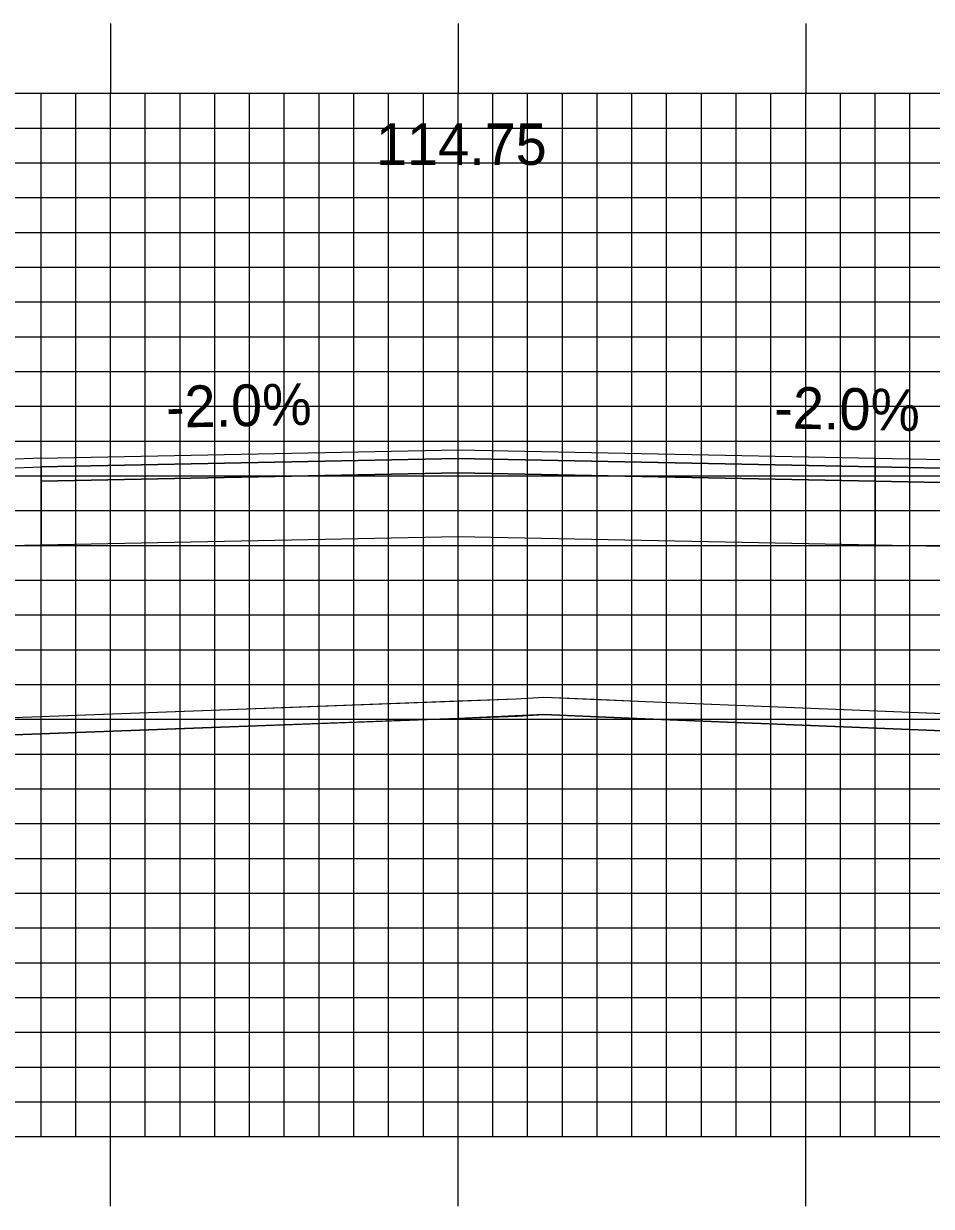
# Model space of a CAD drawing. Extents: x 1754708 to 1755051, y 442591 to 442811.
# Drawn here: x 1754861.02 to 1754887.13, y 442685.31 to 442719.32 of the extents above; entities that cross this region are included whole.
import ezdxf

# ---------------------------------------------------------------- set-up
doc = ezdxf.new("R2010")
doc.units = 0
for name, color, linetype in [('ANNOTATION', 7, 'Continuous'), ('D_Roadway_Centerline', 7, 'Continuous'), ('D_Roadway_Centerline_Text', 7, 'Continuous'), ('D_Roadway_Edge_Shoulder', 7, 'Continuous'), ('D_Roadway_Edge_TW', 7, 'Continuous'), ('D_Roadway_Pavement', 7, 'Continuous'), ('D_Roadway_SubGrade', 7, 'Continuous'), ('GRUBBING IN FILL', 7, 'Continuous'), ('MAJOR', 7, 'Continuous'), ('MINOR', 7, 'Continuous'), ('S_Roadway_Centerline', 7, 'Continuous')]:
    doc.layers.add(name, color=color, linetype=linetype)

msp = doc.modelspace()

# ---------------------------------------------------------------- linework, layer by layer
at = {"layer": 'D_Roadway_Edge_Shoulder'}
msp.add_lwpolyline([(1754861.517, 442706.822), (1754853.517, 442706.502), (1754853.517, 442706.252), (1754861.517, 442706.572)], close=True, dxfattribs=at)
at = {"layer": 'D_Roadway_Edge_TW'}
for points in [[(1754861.517, 442706.572), (1754861.517, 442706.822), (1754873.517, 442707.062), (1754885.517, 442706.822), (1754885.517, 442706.572), (1754873.517, 442706.812)], [(1754885.517, 442706.822), (1754896.317, 442706.606), (1754896.317, 442706.356), (1754885.517, 442706.572)]]:
    msp.add_lwpolyline(points, close=True, dxfattribs=at)
at = {"layer": 'D_Roadway_Pavement'}
for points in [[(1754861.517, 442706.156), (1754861.517, 442706.572), (1754873.517, 442706.812), (1754885.517, 442706.572), (1754885.517, 442706.156), (1754873.517, 442706.396)], [(1754885.517, 442706.572), (1754896.317, 442706.356), (1754896.317, 442705.94), (1754885.517, 442706.156)]]:
    msp.add_lwpolyline(points, close=True, dxfattribs=at)
at = {"layer": 'D_Roadway_SubGrade'}
for points in [[(1754853.517, 442706.252), (1754861.517, 442706.572), (1754861.517, 442706.156), (1754861.517, 442704.322), (1754843.343, 442703.959), (1754853.517, 442706.502)], [(1754861.517, 442704.322), (1754861.517, 442706.156), (1754873.517, 442706.396), (1754885.517, 442706.156), (1754885.517, 442704.322), (1754873.517, 442704.562)], [(1754885.517, 442706.156), (1754896.317, 442705.94), (1754896.317, 442704.106), (1754885.517, 442704.322)]]:
    msp.add_lwpolyline(points, close=True, dxfattribs=at)
at = {"layer": 'GRUBBING IN FILL'}
for points in [[(1754843.343, 442701.662), (1754843.343, 442702.173), (1754848.972, 442700.973), (1754852.257, 442700.236), (1754853.265, 442699.855), (1754854.274, 442699.473), (1754855.953, 442699.362), (1754857.632, 442699.25), (1754866.413, 442699.576), (1754873.517, 442699.839), (1754873.517, 442699.338), (1754866.422, 442699.076), (1754857.625, 442698.75), (1754854.166, 442698.979), (1754852.113, 442699.756)], [(1754843.343, 442701.662), (1754843.343, 442702.173), (1754848.972, 442700.973), (1754852.257, 442700.236), (1754853.265, 442699.855), (1754854.274, 442699.473), (1754855.953, 442699.362), (1754857.632, 442699.25), (1754866.413, 442699.576), (1754873.517, 442699.839), (1754873.517, 442699.338), (1754866.422, 442699.076), (1754857.625, 442698.75), (1754854.166, 442698.979), (1754852.113, 442699.756)], [(1754873.517, 442699.839), (1754875.194, 442699.901), (1754875.979, 442699.949), (1754877.443, 442699.888), (1754878.907, 442699.828), (1754887.476, 442699.48), (1754896.045, 442699.132), (1754900.089, 442699.107), (1754903.782, 442698.881), (1754907.475, 442698.655), (1754911.045, 442698.523), (1754914.492, 442698.396), (1754914.492, 442697.896), (1754910.971, 442698.026), (1754907.451, 442698.155), (1754903.761, 442698.381), (1754900.072, 442698.607), (1754896.033, 442698.632), (1754887.459, 442698.98), (1754878.886, 442699.328), (1754875.984, 442699.448), (1754873.517, 442699.338)], [(1754873.517, 442699.839), (1754875.194, 442699.901), (1754875.979, 442699.949), (1754877.443, 442699.888), (1754878.907, 442699.828), (1754887.476, 442699.48), (1754896.045, 442699.132), (1754900.089, 442699.107), (1754903.782, 442698.881), (1754907.475, 442698.655), (1754911.045, 442698.523), (1754914.492, 442698.396), (1754914.492, 442697.896), (1754910.971, 442698.026), (1754907.451, 442698.155), (1754903.761, 442698.381), (1754900.072, 442698.607), (1754896.033, 442698.632), (1754887.459, 442698.98), (1754878.886, 442699.328), (1754875.984, 442699.448), (1754873.517, 442699.338)]]:
    msp.add_lwpolyline(points, close=True, dxfattribs=at)
msp.add_lwpolyline([(1754843.343, 442701.662), (1754848.865, 442700.485), (1754852.113, 442699.756), (1754854.166, 442698.979), (1754857.625, 442698.75), (1754875.218, 442699.401), (1754875.984, 442699.448), (1754878.886, 442699.328), (1754896.033, 442698.632), (1754900.072, 442698.607), (1754907.451, 442698.155), (1754914.492, 442697.896)], dxfattribs=at)
msp.add_lwpolyline([(1754843.343, 442701.662), (1754848.865, 442700.485), (1754852.113, 442699.756), (1754854.166, 442698.979), (1754857.625, 442698.75), (1754875.218, 442699.401), (1754875.984, 442699.448), (1754878.886, 442699.328), (1754896.033, 442698.632), (1754900.072, 442698.607), (1754907.451, 442698.155), (1754914.492, 442697.896)], dxfattribs=at)
at = {"layer": 'MAJOR'}
for p, q in [((1754863.517, 442719.316), (1754863.517, 442717.312)), ((1754873.517, 442719.316), (1754873.517, 442717.312)), ((1754883.517, 442719.316), (1754883.517, 442717.312)), ((1754733.517, 442717.312), (1755013.517, 442717.312)), ((1754733.517, 442717.312), (1755013.517, 442717.312)), ((1754863.517, 442687.312), (1754863.517, 442717.312)), ((1754873.517, 442687.312), (1754873.517, 442717.312)), ((1754883.517, 442687.312), (1754883.517, 442717.312)), ((1754733.517, 442712.312), (1755013.517, 442712.312)), ((1754733.517, 442707.312), (1755013.517, 442707.312)), ((1754733.517, 442702.312), (1755013.517, 442702.312)), ((1754733.517, 442697.312), (1755013.517, 442697.312)), ((1754733.517, 442692.312), (1755013.517, 442692.312)), ((1754733.517, 442687.312), (1755013.517, 442687.312)), ((1754733.517, 442687.312), (1755013.517, 442687.312)), ((1754863.517, 442685.308), (1754863.517, 442687.312)), ((1754873.517, 442685.308), (1754873.517, 442687.312)), ((1754883.517, 442685.308), (1754883.517, 442687.312))]:
    msp.add_line(p, q, dxfattribs=at)
at = {"layer": 'MINOR'}
for p, q in [((1754861.517, 442687.312), (1754861.517, 442717.312)), ((1754862.517, 442687.312), (1754862.517, 442717.312)), ((1754864.517, 442687.312), (1754864.517, 442717.312)), ((1754865.517, 442687.312), (1754865.517, 442717.312)), ((1754866.517, 442687.312), (1754866.517, 442717.312)), ((1754867.517, 442687.312), (1754867.517, 442717.312)), ((1754868.517, 442687.312), (1754868.517, 442717.312)), ((1754869.517, 442687.312), (1754869.517, 442717.312)), ((1754870.517, 442687.312), (1754870.517, 442717.312)), ((1754871.517, 442687.312), (1754871.517, 442717.312)), ((1754872.517, 442687.312), (1754872.517, 442717.312)), ((1754874.517, 442687.312), (1754874.517, 442717.312)), ((1754875.517, 442687.312), (1754875.517, 442717.312)), ((1754876.517, 442687.312), (1754876.517, 442717.312)), ((1754877.517, 442687.312), (1754877.517, 442717.312)), ((1754878.517, 442687.312), (1754878.517, 442717.312)), ((1754879.517, 442687.312), (1754879.517, 442717.312)), ((1754880.517, 442687.312), (1754880.517, 442717.312)), ((1754881.517, 442687.312), (1754881.517, 442717.312)), ((1754882.517, 442687.312), (1754882.517, 442717.312)), ((1754884.517, 442687.312), (1754884.517, 442717.312)), ((1754885.517, 442687.312), (1754885.517, 442717.312)), ((1754886.517, 442687.312), (1754886.517, 442717.312)), ((1754733.517, 442716.312), (1755013.517, 442716.312)), ((1754733.517, 442715.312), (1755013.517, 442715.312)), ((1754733.517, 442714.312), (1755013.517, 442714.312)), ((1754733.517, 442713.312), (1755013.517, 442713.312)), ((1754733.517, 442711.312), (1755013.517, 442711.312)), ((1754733.517, 442710.312), (1755013.517, 442710.312)), ((1754733.517, 442709.312), (1755013.517, 442709.312)), ((1754733.517, 442708.312), (1755013.517, 442708.312)), ((1754733.517, 442706.312), (1755013.517, 442706.312)), ((1754733.517, 442705.312), (1755013.517, 442705.312)), ((1754733.517, 442704.312), (1755013.517, 442704.312)), ((1754733.517, 442703.312), (1755013.517, 442703.312)), ((1754733.517, 442701.312), (1755013.517, 442701.312)), ((1754733.517, 442700.312), (1755013.517, 442700.312)), ((1754733.517, 442699.312), (1755013.517, 442699.312)), ((1754733.517, 442698.312), (1755013.517, 442698.312)), ((1754733.517, 442696.312), (1755013.517, 442696.312)), ((1754733.517, 442695.312), (1755013.517, 442695.312)), ((1754733.517, 442694.312), (1755013.517, 442694.312)), ((1754733.517, 442693.312), (1755013.517, 442693.312)), ((1754733.517, 442691.312), (1755013.517, 442691.312)), ((1754733.517, 442690.312), (1755013.517, 442690.312)), ((1754733.517, 442689.312), (1755013.517, 442689.312)), ((1754733.517, 442688.312), (1755013.517, 442688.312))]:
    msp.add_line(p, q, dxfattribs=at)
at = {"layer": 'S_Roadway_Centerline'}
msp.add_lwpolyline([(1754820.805, 442707.13), (1754822.854, 442706.77), (1754825.067, 442706.33), (1754826.524, 442706.037), (1754828.077, 442705.984), (1754832.676, 442704.446), (1754848.972, 442700.973), (1754852.257, 442700.236), (1754854.274, 442699.473), (1754857.632, 442699.25), (1754875.194, 442699.901), (1754875.979, 442699.949), (1754878.907, 442699.828), (1754896.045, 442699.132), (1754900.089, 442699.107), (1754907.475, 442698.655), (1754914.615, 442698.392), (1754927.562, 442698.332), (1754934.194, 442698.29), (1754935.534, 442698.264), (1754937.831, 442698.209), (1754947.484, 442697.842), (1754953.043, 442697.646), (1754970.333, 442697)], dxfattribs=at)

# ---------------------------------------------------------------- texts
at = {"layer": 'ANNOTATION'}
for rotation, p in [(1.1458, (1754865.124, 442707.695)), (358.8542, (1754882.604, 442707.681))]:
    msp.add_text('-2.0%', height=1.2, rotation=rotation, dxfattribs=at).set_placement(p)
at = {"layer": 'D_Roadway_Centerline'}
for s, p in [('C', (1754873.512, 442707.062)), ('L', (1754873.517, 442707.055))]:
    msp.add_text(s, height=0.0146, dxfattribs=at).set_placement(p)
at = {"layer": 'D_Roadway_Centerline_Text'}
msp.add_text('114.75', height=1.2, dxfattribs=at).set_placement((1754871.158, 442715.253))

doc.saveas('drawing.dxf')
